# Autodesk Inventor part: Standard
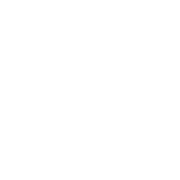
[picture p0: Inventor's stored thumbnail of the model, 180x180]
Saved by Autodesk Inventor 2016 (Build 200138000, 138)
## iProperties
Created: 2005-05
Part Number: Standard
Document SubType Name: Modeling
Designer: JWe
Density: 1 g/cm^3
Material: Generic
Appearance: Default
Author: JWe
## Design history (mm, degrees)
